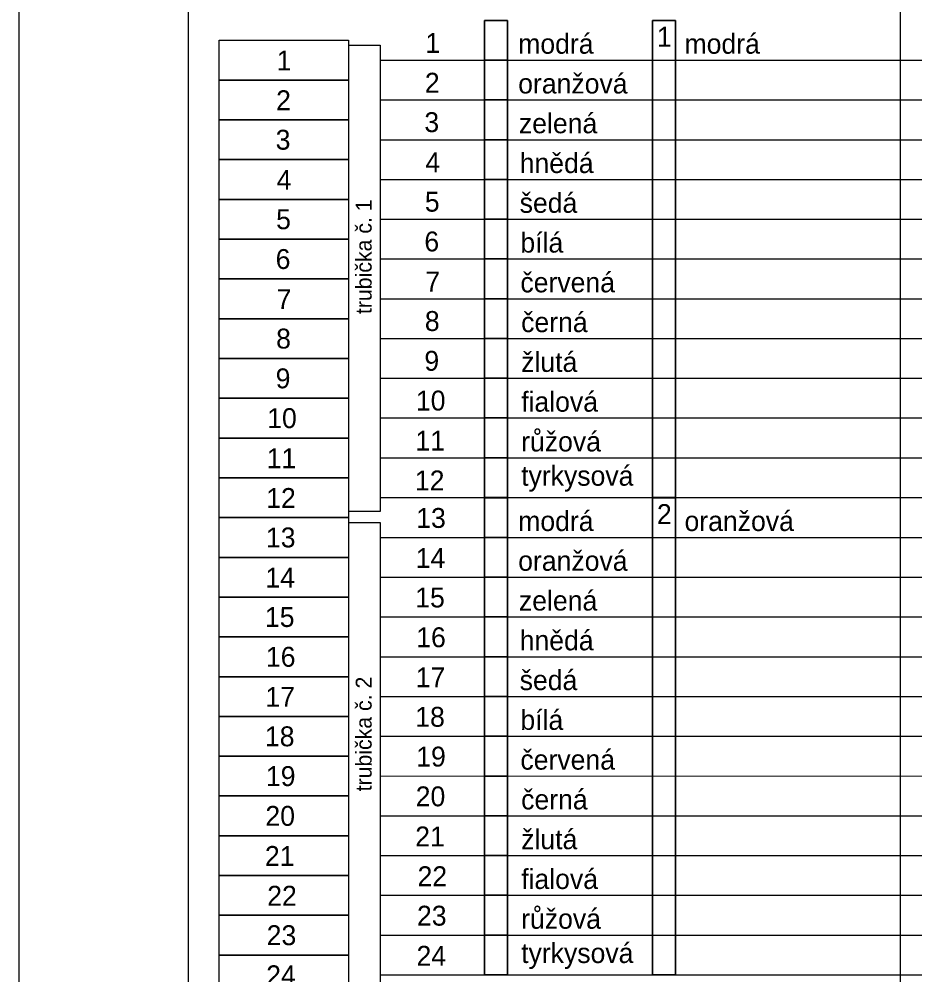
# Model space of a CAD drawing. Extents: x 1901 to 2519, y -3585 to -3154.
# Drawn here: x 1901.2 to 1980.5, y -3287.5 to -3202.9 of the extents above; entities that cross this region are included whole.
import ezdxf

# ---------------------------------------------------------------- set-up
doc = ezdxf.new("R2010")
doc.units = 0
doc.layers.add('rozvláknění', color=7, linetype='Continuous')
doc.layers.add('Vrstva 4', color=7, linetype='Continuous')

msp = doc.modelspace()

# ---------------------------------------------------------------- linework, layer by layer
at = {"layer": 'rozvláknění'}
for p, q in [((1930.388, -3206.524), (1930.406, -3206.524)), ((1933.193, -3206.524), (2025.898, -3206.527)), ((1930.388, -3210.044), (1930.406, -3210.044)), ((1933.193, -3210.043), (2025.898, -3210.045)), ((1930.388, -3213.564), (1930.406, -3213.564)), ((1933.193, -3213.561), (2025.898, -3213.563)), ((1933.193, -3213.564), (1933.193, -3217.084)), ((1930.388, -3217.084), (1930.406, -3217.084)), ((1933.193, -3217.079), (2025.898, -3217.081)), ((1930.388, -3220.604), (1930.406, -3220.604)), ((1933.193, -3220.597), (2025.898, -3220.599)), ((1930.388, -3224.124), (1930.406, -3224.124)), ((1933.193, -3224.115), (2025.898, -3224.117)), ((1933.193, -3224.124), (1933.193, -3227.644)), ((1930.388, -3227.644), (1930.406, -3227.644)), ((1933.193, -3227.634), (2025.898, -3227.636)), ((1930.388, -3231.164), (1930.406, -3231.164)), ((1933.193, -3231.152), (2025.898, -3231.154)), ((1930.388, -3234.684), (1930.406, -3234.684)), ((1933.193, -3234.67), (2025.898, -3234.672)), ((1933.193, -3234.684), (1933.193, -3238.204)), ((1930.388, -3238.204), (1930.406, -3238.204)), ((1933.193, -3238.188), (2025.898, -3238.19)), ((1930.388, -3241.724), (1930.406, -3241.724)), ((1933.193, -3241.706), (2025.898, -3241.708)), ((1930.388, -3245.244), (1930.406, -3245.244)), ((1933.193, -3245.225), (2025.898, -3245.227)), ((1930.388, -3248.764), (1930.406, -3248.764)), ((1933.193, -3248.764), (2025.898, -3248.767)), ((1930.388, -3252.284), (1930.406, -3252.284)), ((1933.193, -3252.283), (2025.898, -3252.285)), ((1930.388, -3255.804), (1930.406, -3255.804)), ((1933.193, -3255.801), (2025.898, -3255.803)), ((1933.193, -3255.804), (1933.193, -3259.324)), ((1930.388, -3259.324), (1930.406, -3259.324)), ((1933.193, -3259.319), (2025.898, -3259.321)), ((1930.388, -3262.844), (1930.406, -3262.844)), ((1933.193, -3262.837), (2025.898, -3262.839)), ((1930.388, -3266.364), (1930.406, -3266.364)), ((1933.193, -3266.355), (2025.898, -3266.357)), ((1933.193, -3266.364), (1933.193, -3269.884)), ((1930.388, -3269.884), (1930.406, -3269.884)), ((1933.193, -3269.874), (2025.898, -3269.876)), ((1930.388, -3273.404), (1930.406, -3273.404)), ((1933.193, -3273.392), (2025.898, -3273.394)), ((1930.388, -3276.924), (1930.406, -3276.924)), ((1933.193, -3276.91), (2025.898, -3276.912)), ((1933.193, -3276.924), (1933.193, -3280.444)), ((1930.388, -3280.444), (1930.406, -3280.444)), ((1933.193, -3280.428), (2025.898, -3280.43)), ((1930.388, -3283.964), (1930.406, -3283.964)), ((1933.193, -3283.946), (2025.898, -3283.948)), ((1933.193, -3287.465), (2025.898, -3287.467))]:
    msp.add_line(p, q, dxfattribs=at)
for points in [[(1916.214, -3178.545), (1979.2, -3178.544), (1979.2, -3379.278), (1916.214, -3379.278)], [(1942.405, -3203.008), (1944.446, -3203.008), (1944.446, -3206.527), (1942.405, -3206.527)], [(1959.324, -3245.227), (1957.283, -3245.227), (1957.283, -3203.008), (1959.324, -3203.008)], [(1918.946, -3204.764), (1930.388, -3204.764), (1930.388, -3208.284), (1918.946, -3208.284)], [(1930.406, -3205.199), (1933.193, -3205.199), (1933.193, -3246.458), (1930.406, -3246.458)], [(1942.405, -3206.527), (1944.446, -3206.527), (1944.446, -3210.045), (1942.405, -3210.045)], [(1918.946, -3208.284), (1930.388, -3208.284), (1930.388, -3211.804), (1918.946, -3211.804)], [(1942.405, -3210.045), (1944.446, -3210.045), (1944.446, -3213.563), (1942.405, -3213.563)], [(1918.946, -3211.804), (1930.388, -3211.804), (1930.388, -3215.324), (1918.946, -3215.324)], [(1942.405, -3213.563), (1944.446, -3213.563), (1944.446, -3217.081), (1942.405, -3217.081)], [(1918.946, -3215.324), (1930.388, -3215.324), (1930.388, -3218.844), (1918.946, -3218.844)], [(1942.405, -3217.081), (1944.446, -3217.081), (1944.446, -3220.599), (1942.405, -3220.599)], [(1918.946, -3218.844), (1930.388, -3218.844), (1930.388, -3222.364), (1918.946, -3222.364)], [(1942.405, -3220.599), (1944.446, -3220.599), (1944.446, -3224.117), (1942.405, -3224.117)], [(1918.946, -3222.364), (1930.388, -3222.364), (1930.388, -3225.884), (1918.946, -3225.884)], [(1942.405, -3224.117), (1944.446, -3224.117), (1944.446, -3227.636), (1942.405, -3227.636)], [(1918.946, -3225.884), (1930.388, -3225.884), (1930.388, -3229.404), (1918.946, -3229.404)], [(1942.405, -3227.636), (1944.446, -3227.636), (1944.446, -3231.154), (1942.405, -3231.154)], [(1918.946, -3229.404), (1930.388, -3229.404), (1930.388, -3232.924), (1918.946, -3232.924)], [(1942.405, -3231.154), (1944.446, -3231.154), (1944.446, -3234.672), (1942.405, -3234.672)], [(1918.946, -3232.924), (1930.388, -3232.924), (1930.388, -3236.444), (1918.946, -3236.444)], [(1942.405, -3234.672), (1944.446, -3234.672), (1944.446, -3238.19), (1942.405, -3238.19)], [(1918.946, -3236.444), (1930.388, -3236.444), (1930.388, -3239.964), (1918.946, -3239.964)], [(1942.405, -3238.19), (1944.446, -3238.19), (1944.446, -3241.708), (1942.405, -3241.708)], [(1918.946, -3239.964), (1930.388, -3239.964), (1930.388, -3243.484), (1918.946, -3243.484)], [(1942.405, -3241.708), (1944.446, -3241.708), (1944.446, -3245.227), (1942.405, -3245.227)], [(1918.946, -3243.484), (1930.388, -3243.484), (1930.388, -3247.004), (1918.946, -3247.004)], [(1942.405, -3245.248), (1944.446, -3245.248), (1944.446, -3248.767), (1942.405, -3248.767)], [(1959.324, -3287.467), (1957.283, -3287.467), (1957.283, -3245.248), (1959.324, -3245.248)], [(1918.946, -3247.004), (1930.388, -3247.004), (1930.388, -3250.524), (1918.946, -3250.524)], [(1930.406, -3247.439), (1933.193, -3247.439), (1933.193, -3288.698), (1930.406, -3288.698)], [(1942.405, -3248.767), (1944.446, -3248.767), (1944.446, -3252.285), (1942.405, -3252.285)], [(1918.946, -3250.524), (1930.388, -3250.524), (1930.388, -3254.044), (1918.946, -3254.044)], [(1942.405, -3252.285), (1944.446, -3252.285), (1944.446, -3255.803), (1942.405, -3255.803)], [(1918.946, -3254.044), (1930.388, -3254.044), (1930.388, -3257.564), (1918.946, -3257.564)], [(1942.405, -3255.803), (1944.446, -3255.803), (1944.446, -3259.321), (1942.405, -3259.321)], [(1918.946, -3257.564), (1930.388, -3257.564), (1930.388, -3261.084), (1918.946, -3261.084)], [(1942.405, -3259.321), (1944.446, -3259.321), (1944.446, -3262.839), (1942.405, -3262.839)], [(1918.946, -3261.084), (1930.388, -3261.084), (1930.388, -3264.604), (1918.946, -3264.604)], [(1942.405, -3262.839), (1944.446, -3262.839), (1944.446, -3266.357), (1942.405, -3266.357)], [(1918.946, -3264.604), (1930.388, -3264.604), (1930.388, -3268.124), (1918.946, -3268.124)], [(1942.405, -3266.357), (1944.446, -3266.357), (1944.446, -3269.876), (1942.405, -3269.876)], [(1918.946, -3268.124), (1930.388, -3268.124), (1930.388, -3271.644), (1918.946, -3271.644)], [(1942.405, -3269.876), (1944.446, -3269.876), (1944.446, -3273.394), (1942.405, -3273.394)], [(1918.946, -3271.644), (1930.388, -3271.644), (1930.388, -3275.164), (1918.946, -3275.164)], [(1942.405, -3273.394), (1944.446, -3273.394), (1944.446, -3276.912), (1942.405, -3276.912)], [(1918.946, -3275.164), (1930.388, -3275.164), (1930.388, -3278.684), (1918.946, -3278.684)], [(1942.405, -3276.912), (1944.446, -3276.912), (1944.446, -3280.43), (1942.405, -3280.43)], [(1918.946, -3278.684), (1930.388, -3278.684), (1930.388, -3282.204), (1918.946, -3282.204)], [(1942.405, -3280.43), (1944.446, -3280.43), (1944.446, -3283.948), (1942.405, -3283.948)], [(1918.946, -3282.204), (1930.388, -3282.204), (1930.388, -3285.724), (1918.946, -3285.724)], [(1942.405, -3283.948), (1944.446, -3283.948), (1944.446, -3287.467), (1942.405, -3287.467)], [(1918.946, -3285.724), (1930.388, -3285.724), (1930.388, -3289.244), (1918.946, -3289.244)]]:
    msp.add_lwpolyline(points, close=True, dxfattribs=at)
for points in [[(1942.405, -3206.527), (1944.446, -3206.527), (1944.446, -3203.008), (1942.405, -3203.008), (1942.405, -3206.527)], [(1959.324, -3203.008), (1957.283, -3203.008), (1957.283, -3245.227), (1959.324, -3245.227), (1959.324, -3203.008)], [(1942.405, -3210.045), (1944.446, -3210.045), (1944.446, -3206.527), (1942.405, -3206.527), (1942.405, -3210.045)], [(1942.405, -3213.563), (1944.446, -3213.563), (1944.446, -3210.045), (1942.405, -3210.045), (1942.405, -3213.563)], [(1942.405, -3217.081), (1944.446, -3217.081), (1944.446, -3213.563), (1942.405, -3213.563), (1942.405, -3217.081)], [(1942.405, -3220.599), (1944.446, -3220.599), (1944.446, -3217.081), (1942.405, -3217.081), (1942.405, -3220.599)], [(1942.405, -3224.117), (1944.446, -3224.117), (1944.446, -3220.599), (1942.405, -3220.599), (1942.405, -3224.117)], [(1942.405, -3227.636), (1944.446, -3227.636), (1944.446, -3224.117), (1942.405, -3224.117), (1942.405, -3227.636)], [(1942.405, -3231.154), (1944.446, -3231.154), (1944.446, -3227.636), (1942.405, -3227.636), (1942.405, -3231.154)], [(1942.405, -3234.672), (1944.446, -3234.672), (1944.446, -3231.154), (1942.405, -3231.154), (1942.405, -3234.672)], [(1942.405, -3238.19), (1944.446, -3238.19), (1944.446, -3234.672), (1942.405, -3234.672), (1942.405, -3238.19)], [(1942.405, -3241.708), (1944.446, -3241.708), (1944.446, -3238.19), (1942.405, -3238.19), (1942.405, -3241.708)], [(1942.405, -3245.227), (1944.446, -3245.227), (1944.446, -3241.708), (1942.405, -3241.708), (1942.405, -3245.227)], [(1942.405, -3248.767), (1944.446, -3248.767), (1944.446, -3245.248), (1942.405, -3245.248), (1942.405, -3248.767)], [(1959.324, -3245.248), (1957.283, -3245.248), (1957.283, -3287.467), (1959.324, -3287.467), (1959.324, -3245.248)], [(1942.405, -3252.285), (1944.446, -3252.285), (1944.446, -3248.767), (1942.405, -3248.767), (1942.405, -3252.285)], [(1942.405, -3255.803), (1944.446, -3255.803), (1944.446, -3252.285), (1942.405, -3252.285), (1942.405, -3255.803)], [(1942.405, -3259.321), (1944.446, -3259.321), (1944.446, -3255.803), (1942.405, -3255.803), (1942.405, -3259.321)], [(1942.405, -3262.839), (1944.446, -3262.839), (1944.446, -3259.321), (1942.405, -3259.321), (1942.405, -3262.839)], [(1942.405, -3266.357), (1944.446, -3266.357), (1944.446, -3262.839), (1942.405, -3262.839), (1942.405, -3266.357)], [(1942.405, -3269.876), (1944.446, -3269.876), (1944.446, -3266.357), (1942.405, -3266.357), (1942.405, -3269.876)], [(1942.405, -3273.394), (1944.446, -3273.394), (1944.446, -3269.876), (1942.405, -3269.876), (1942.405, -3273.394)], [(1942.405, -3276.912), (1944.446, -3276.912), (1944.446, -3273.394), (1942.405, -3273.394), (1942.405, -3276.912)], [(1942.405, -3280.43), (1944.446, -3280.43), (1944.446, -3276.912), (1942.405, -3276.912), (1942.405, -3280.43)], [(1942.405, -3283.948), (1944.446, -3283.948), (1944.446, -3280.43), (1942.405, -3280.43), (1942.405, -3283.948)], [(1942.405, -3287.467), (1944.446, -3287.467), (1944.446, -3283.948), (1942.405, -3283.948), (1942.405, -3287.467)]]:
    msp.add_lwpolyline(points, dxfattribs=at)
at = {"layer": 'Vrstva 4'}
msp.add_lwpolyline([(1901.224, -3154.468), (2516.224, -3154.468), (2516.224, -3584.968), (1901.224, -3584.968)], close=True, dxfattribs=at)

# ---------------------------------------------------------------- texts
at = {"layer": 'rozvláknění'}
for s, p in [('1', (1957.681, -3205.334)), ('1', (1937.185, -3205.88)), ('modrá', (1945.401, -3205.953)), ('modrá', (1960.122, -3205.953)), ('1', (1924.022, -3207.433)), ('2', (1937.139, -3209.4)), ('oranžová', (1945.401, -3209.473)), ('2', (1923.975, -3210.953)), ('3', (1937.097, -3212.89)), ('zelená', (1945.467, -3212.993)), ('3', (1923.933, -3214.444)), ('4', (1937.185, -3216.44)), ('hnědá', (1945.532, -3216.513)), ('4', (1924.022, -3217.993)), ('5', (1937.139, -3219.93)), ('šedá', (1945.532, -3220.033)), ('5', (1923.975, -3221.484)), ('6', (1937.097, -3223.45)), ('bílá', (1945.597, -3223.553)), ('6', (1923.933, -3225.004)), ('červená', (1945.597, -3227.073)), ('7', (1937.185, -3227)), ('7', (1924.022, -3228.553)), ('8', (1937.139, -3230.49)), ('černá', (1945.663, -3230.593)), ('8', (1923.975, -3232.044)), ('9', (1937.097, -3234.01)), ('žlutá', (1945.663, -3234.113)), ('9', (1923.933, -3235.564)), ('10', (1936.348, -3237.53)), ('fialová', (1945.663, -3237.633)), ('10', (1923.185, -3239.084)), ('11', (1936.302, -3241.08)), ('růžová', (1945.663, -3241.153)), ('11', (1923.138, -3242.633)), ('12', (1936.26, -3244.6)), ('tyrkysová', (1945.663, -3244.185)), ('12', (1923.096, -3246.153)), ('13', (1936.377, -3247.917)), ('modrá', (1945.401, -3248.193)), ('2', (1957.681, -3247.574)), ('oranžová', (1960.122, -3248.193)), ('13', (1923.072, -3249.644)), ('14', (1936.33, -3251.466)), ('oranžová', (1945.401, -3251.713)), ('14', (1923.025, -3253.193)), ('15', (1936.288, -3254.957)), ('zelená', (1945.467, -3255.233)), ('15', (1922.983, -3256.684)), ('16', (1936.377, -3258.477)), ('hnědá', (1945.532, -3258.753)), ('16', (1923.072, -3260.204)), ('17', (1936.33, -3262.026)), ('šedá', (1945.532, -3262.273)), ('17', (1923.025, -3263.753)), ('18', (1936.288, -3265.517)), ('bílá', (1945.597, -3265.793)), ('18', (1922.983, -3267.244)), ('19', (1936.377, -3269.037)), ('červená', (1945.597, -3269.313)), ('19', (1923.072, -3270.764)), ('20', (1936.33, -3272.557)), ('černá', (1945.663, -3272.833)), ('20', (1923.025, -3274.284)), ('21', (1936.288, -3276.106)), ('žlutá', (1945.663, -3276.353)), ('21', (1922.983, -3277.833)), ('22', (1936.491, -3279.626)), ('fialová', (1945.663, -3279.873)), ('22', (1923.185, -3281.353)), ('23', (1936.444, -3283.117)), ('růžová', (1945.663, -3283.393)), ('23', (1923.138, -3284.844)), ('24', (1936.402, -3286.666)), ('tyrkysová', (1945.663, -3286.425)), ('24', (1923.096, -3288.393))]:
    msp.add_text(s, height=1.76, dxfattribs=at).set_placement(p)
for s, p in [('trubička č. 1', (1932.428, -3228.997)), ('trubička č. 2', (1932.428, -3271.237))]:
    msp.add_text(s, height=1.408, rotation=90, dxfattribs=at).set_placement(p)

doc.saveas('drawing.dxf')
